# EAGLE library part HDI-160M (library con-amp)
AMP connector
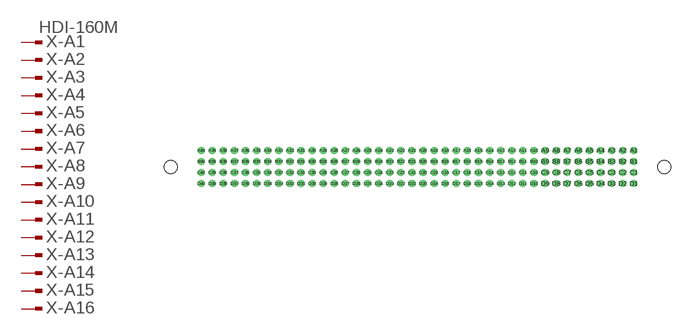
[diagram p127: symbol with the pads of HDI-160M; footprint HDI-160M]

Designator prefix X; gates -A1=PIN-MV -A2=PIN-M -A3=PIN-M -A4=PIN-M -A5=PIN-M -A6=PIN-M -A7=PIN-M -A8=PIN-M -A9=PIN-M -A10=PIN-M -A11=PIN-M -A12=PIN-M -A13=PIN-M -A14=PIN-M -A15=PIN-M -A16=PIN-M -A17=PIN-M -A18=PIN-M -A19=PIN-M -A20=PIN-M -A21=PIN-M -A22=PIN-M -A23=PIN-M -A24=PIN-M -A25=PIN-M -A26=PIN-M -A27=PIN-M -A28=PIN-M -A29=PIN-M -A30=PIN-M -A31=PIN-M -A32=PIN-M -A33=PIN-M -A34=PIN-M -A35=PIN-M -A36=PIN-M -A37=PIN-M -A38=PIN-M -A39=PIN-M -A40=PIN-M -B1=PIN-MV -B2=PIN-M -B3=PIN-M -B4=PIN-M -B5=PIN-M -B6=PIN-M -B7=PIN-M -B8=PIN-M -B9=PIN-M -B10=PIN-M -B11=PIN-M -B12=PIN-M -B13=PIN-M -B14=PIN-M -B15=PIN-M -B16=PIN-M -B17=PIN-M -B18=PIN-M -B19=PIN-M -B20=PIN-M -B21=PIN-M -B22=PIN-M -B23=PIN-M -B24=PIN-M -B25=PIN-M -B26=PIN-M -B27=PIN-M -B28=PIN-M -B29=PIN-M -B30=PIN-M -B31=PIN-M -B32=PIN-M -B33=PIN-M -B34=PIN-M -B35=PIN-M -B36=PIN-M -B37=PIN-M -B38=PIN-M -B39=PIN-M -B40=PIN-M -C1=PIN-MV -C2=PIN-M -C3=PIN-M -C4=PIN-M -C5=PIN-M -C6=PIN-M -C7=PIN-M -C8=PIN-M -C9=PIN-M -C10=PIN-M -C11=PIN-M -C12=PIN-M -C13=PIN-M -C14=PIN-M -C15=PIN-M -C16=PIN-M -C17=PIN-M -C18=PIN-M -C19=PIN-M -C20=PIN-M -C21=PIN-M -C22=PIN-M -C23=PIN-M -C24=PIN-M -C25=PIN-M -C26=PIN-M -C27=PIN-M -C28=PIN-M -C29=PIN-M -C30=PIN-M -C31=PIN-M -C32=PIN-M -C33=PIN-M -C34=PIN-M -C35=PIN-M -C36=PIN-M -C37=PIN-M -C38=PIN-M -C39=PIN-M -C40=PIN-M -D1=PIN-MV -D2=PIN-M -D3=PIN-M -D4=PIN-M -D5=PIN-M -D6=PIN-M -D7=PIN-M -D8=PIN-M -D9=PIN-M -D10=PIN-M -D11=PIN-M -D12=PIN-M -D13=PIN-M -D14=PIN-M -D15=PIN-M -D16=PIN-M -D17=PIN-M -D18=PIN-M -D19=PIN-M -D20=PIN-M -D21=PIN-M -D22=PIN-M -D23=PIN-M -D24=PIN-M -D25=PIN-M -D26=PIN-M -D27=PIN-M -D28=PIN-M -D29=PIN-M -D30=PIN-M -D31=PIN-M -D32=PIN-M -D33=PIN-M -D34=PIN-M -D35=PIN-M -D36=PIN-M -D37=PIN-M -D38=PIN-M -D39=PIN-M -D40=PIN-M

## HDI-160M (OC_FARNELL: unknown; OC_NEWARK: unknown)  [HDI-160M]
A1  -A1:1  pas
A2  -A2:1  pas
A3  -A3:1  pas
A4  -A4:1  pas
A5  -A5:1  pas
A6  -A6:1  pas
A7  -A7:1  pas
A8  -A8:1  pas
A9  -A9:1  pas
A10  -A10:1  pas
A11  -A11:1  pas
A12  -A12:1  pas
A13  -A13:1  pas
A14  -A14:1  pas
A15  -A15:1  pas
A16  -A16:1  pas
A17  -A17:1  pas
A18  -A18:1  pas
A19  -A19:1  pas
A20  -A20:1  pas
A21  -A21:1  pas
A22  -A22:1  pas
A23  -A23:1  pas
A24  -A24:1  pas
A25  -A25:1  pas
A26  -A26:1  pas
A27  -A27:1  pas
A28  -A28:1  pas
A29  -A29:1  pas
A30  -A30:1  pas
A31  -A31:1  pas
A32  -A32:1  pas
A33  -A33:1  pas
A34  -A34:1  pas
A35  -A35:1  pas
A36  -A36:1  pas
A37  -A37:1  pas
A38  -A38:1  pas
A39  -A39:1  pas
A40  -A40:1  pas
B1  -B1:1  pas
B2  -B2:1  pas
B3  -B3:1  pas
B4  -B4:1  pas
B5  -B5:1  pas
B6  -B6:1  pas
B7  -B7:1  pas
B8  -B8:1  pas
B9  -B9:1  pas
B10  -B10:1  pas
B11  -B11:1  pas
B12  -B12:1  pas
B13  -B13:1  pas
B14  -B14:1  pas
B15  -B15:1  pas
B16  -B16:1  pas
B17  -B17:1  pas
B18  -B18:1  pas
B19  -B19:1  pas
B20  -B20:1  pas
B21  -B21:1  pas
B22  -B22:1  pas
B23  -B23:1  pas
B24  -B24:1  pas
B25  -B25:1  pas
B26  -B26:1  pas
B27  -B27:1  pas
B28  -B28:1  pas
B29  -B29:1  pas
B30  -B30:1  pas
B31  -B31:1  pas
B32  -B32:1  pas
B33  -B33:1  pas
B34  -B34:1  pas
B35  -B35:1  pas
B36  -B36:1  pas
B37  -B37:1  pas
B38  -B38:1  pas
B39  -B39:1  pas
B40  -B40:1  pas
C1  -C1:1  pas
C2  -C2:1  pas
C3  -C3:1  pas
C4  -C4:1  pas
C5  -C5:1  pas
C6  -C6:1  pas
C7  -C7:1  pas
C8  -C8:1  pas
C9  -C9:1  pas
C10  -C10:1  pas
C11  -C11:1  pas
C12  -C12:1  pas
C13  -C13:1  pas
C14  -C14:1  pas
C15  -C15:1  pas
C16  -C16:1  pas
C17  -C17:1  pas
C18  -C18:1  pas
C19  -C19:1  pas
C20  -C20:1  pas
C21  -C21:1  pas
C22  -C22:1  pas
C23  -C23:1  pas
C24  -C24:1  pas
C25  -C25:1  pas
C26  -C26:1  pas
C27  -C27:1  pas
C28  -C28:1  pas
C29  -C29:1  pas
C30  -C30:1  pas
C31  -C31:1  pas
C32  -C32:1  pas
C33  -C33:1  pas
C34  -C34:1  pas
C35  -C35:1  pas
C36  -C36:1  pas
C37  -C37:1  pas
C38  -C38:1  pas
C39  -C39:1  pas
C40  -C40:1  pas
D1  -D1:1  pas
D2  -D2:1  pas
D3  -D3:1  pas
D4  -D4:1  pas
D5  -D5:1  pas
D6  -D6:1  pas
D7  -D7:1  pas
D8  -D8:1  pas
D9  -D9:1  pas
D10  -D10:1  pas
D11  -D11:1  pas
D12  -D12:1  pas
D13  -D13:1  pas
D14  -D14:1  pas
D15  -D15:1  pas
D16  -D16:1  pas
D17  -D17:1  pas
D18  -D18:1  pas
D19  -D19:1  pas
D20  -D20:1  pas
D21  -D21:1  pas
D22  -D22:1  pas
D23  -D23:1  pas
D24  -D24:1  pas
D25  -D25:1  pas
D26  -D26:1  pas
D27  -D27:1  pas
D28  -D28:1  pas
D29  -D29:1  pas
D30  -D30:1  pas
D31  -D31:1  pas
D32  -D32:1  pas
D33  -D33:1  pas
D34  -D34:1  pas
D35  -D35:1  pas
D36  -D36:1  pas
D37  -D37:1  pas
D38  -D38:1  pas
D39  -D39:1  pas
D40  -D40:1  pas

## Footprint HDI-160M (pad centres in mm)
AMP connector
drill 1.09 octagon: A1 49.53,3.81; A2 46.99,3.81; A3 44.45,3.81; A4 41.91,3.81; A5 39.37,3.81; A6 36.83,3.81; A7 34.29,3.81; A8 31.75,3.81; A9 29.21,3.81; A10 26.67,3.81; A11 24.13,3.81; A12 21.59,3.81; A13 19.05,3.81; A14 16.51,3.81; A15 13.97,3.81; A16 11.43,3.81; A17 8.89,3.81; A18 6.35,3.81; A19 3.81,3.81; A20 1.27,3.81; A21 -1.27,3.81; A22 -3.81,3.81; A23 -6.35,3.81; A24 -8.89,3.81; A25 -11.43,3.81; A26 -13.97,3.81; A27 -16.51,3.81; A28 -19.05,3.81; A29 -21.59,3.81; A30 -24.13,3.81; A31 -26.67,3.81; A32 -29.21,3.81; A33 -31.75,3.81; A34 -34.29,3.81; A35 -36.83,3.81; A36 -39.37,3.81; A37 -41.91,3.81; A38 -44.45,3.81; A39 -46.99,3.81; A40 -49.53,3.81
drill 1.09 round: B1 49.53,1.27; B2 46.99,1.27; B3 44.45,1.27; B4 41.91,1.27; B5 39.37,1.27; B6 36.83,1.27; B7 34.29,1.27; B8 31.75,1.27; B9 29.21,1.27; B10 26.67,1.27; B11 24.13,1.27; B12 21.59,1.27; B13 19.05,1.27; B14 16.51,1.27; B15 13.97,1.27; B16 11.43,1.27; B17 8.89,1.27; B18 6.35,1.27; B19 3.81,1.27; B20 1.27,1.27; B21 -1.27,1.27; B22 -3.81,1.27; B23 -6.35,1.27; B24 -8.89,1.27; B25 -11.43,1.27; B26 -13.97,1.27; B27 -16.51,1.27; B28 -19.05,1.27; B29 -21.59,1.27; B30 -24.13,1.27; B31 -26.67,1.27; B32 -29.21,1.27; B33 -31.75,1.27; B34 -34.29,1.27; B35 -36.83,1.27; B36 -39.37,1.27; B37 -41.91,1.27; B38 -44.45,1.27; B39 -46.99,1.27; B40 -49.53,1.27; C1 49.53,-1.27; C2 46.99,-1.27; C3 44.45,-1.27; C4 41.91,-1.27; C5 39.37,-1.27; C6 36.83,-1.27; C7 34.29,-1.27; C8 31.75,-1.27; C9 29.21,-1.27; C10 26.67,-1.27; C11 24.13,-1.27; C12 21.59,-1.27; C13 19.05,-1.27; C14 16.51,-1.27; C15 13.97,-1.27; C16 11.43,-1.27; C17 8.89,-1.27; C18 6.35,-1.27; C19 3.81,-1.27; C20 1.27,-1.27; C21 -1.27,-1.27; C22 -3.81,-1.27; C23 -6.35,-1.27; C24 -8.89,-1.27; C25 -11.43,-1.27; C26 -13.97,-1.27; C27 -16.51,-1.27; C28 -19.05,-1.27; C29 -21.59,-1.27; C30 -24.13,-1.27; C31 -26.67,-1.27; C32 -29.21,-1.27; C33 -31.75,-1.27; C34 -34.29,-1.27; C35 -36.83,-1.27; C36 -39.37,-1.27; C37 -41.91,-1.27; C38 -44.45,-1.27; C39 -46.99,-1.27; C40 -49.53,-1.27; D1 49.53,-3.81; D2 46.99,-3.81; D3 44.45,-3.81; D4 41.91,-3.81; D5 39.37,-3.81; D6 36.83,-3.81; D7 34.29,-3.81; D8 31.75,-3.81; D9 29.21,-3.81; D10 26.67,-3.81; D11 24.13,-3.81; D12 21.59,-3.81; D13 19.05,-3.81; D14 16.51,-3.81; D15 13.97,-3.81; D16 11.43,-3.81; D17 8.89,-3.81; D18 6.35,-3.81; D19 3.81,-3.81; D20 1.27,-3.81; D21 -1.27,-3.81; D22 -3.81,-3.81; D23 -6.35,-3.81; D24 -8.89,-3.81; D25 -11.43,-3.81; D26 -13.97,-3.81; D27 -16.51,-3.81; D28 -19.05,-3.81; D29 -21.59,-3.81; D30 -24.13,-3.81; D31 -26.67,-3.81; D32 -29.21,-3.81; D33 -31.75,-3.81; D34 -34.29,-3.81; D35 -36.83,-3.81; D36 -39.37,-3.81; D37 -41.91,-3.81; D38 -44.45,-3.81; D39 -46.99,-3.81; D40 -49.53,-3.81
hole 3.05 at -56.51,0
hole 3.05 at 56.51,0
